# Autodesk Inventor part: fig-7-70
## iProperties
Shininess: 64.0
Length Units: 11269
Angle Units: 11279
Time Units: 11290
Mass Units: 11283
Length Display Precision: 3
Angle Display Precision: 2
Compacted: True
Part Number: fig-7-70
Document SubType Name: Modeling
Created: 2002-12
Designer: deepak
Density: 1 g/cm^3
Density: 0.0
Volumn: 0.0
Area: 0.0
PropertySet Name: Model Information
Control State: 0
Master: False
Checked Out: False
Author: deepak
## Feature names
1. Extrusion1
